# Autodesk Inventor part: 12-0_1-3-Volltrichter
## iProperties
Created: 2006-01
Part Number: 12-0_1-3-Volltrichter
Document SubType Name: Modeling
Designer: Armin Gräf
Stock Number: 12-0_1-3-Volltrichter
Author: Armin Gräf
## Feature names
1. Erhebung1
